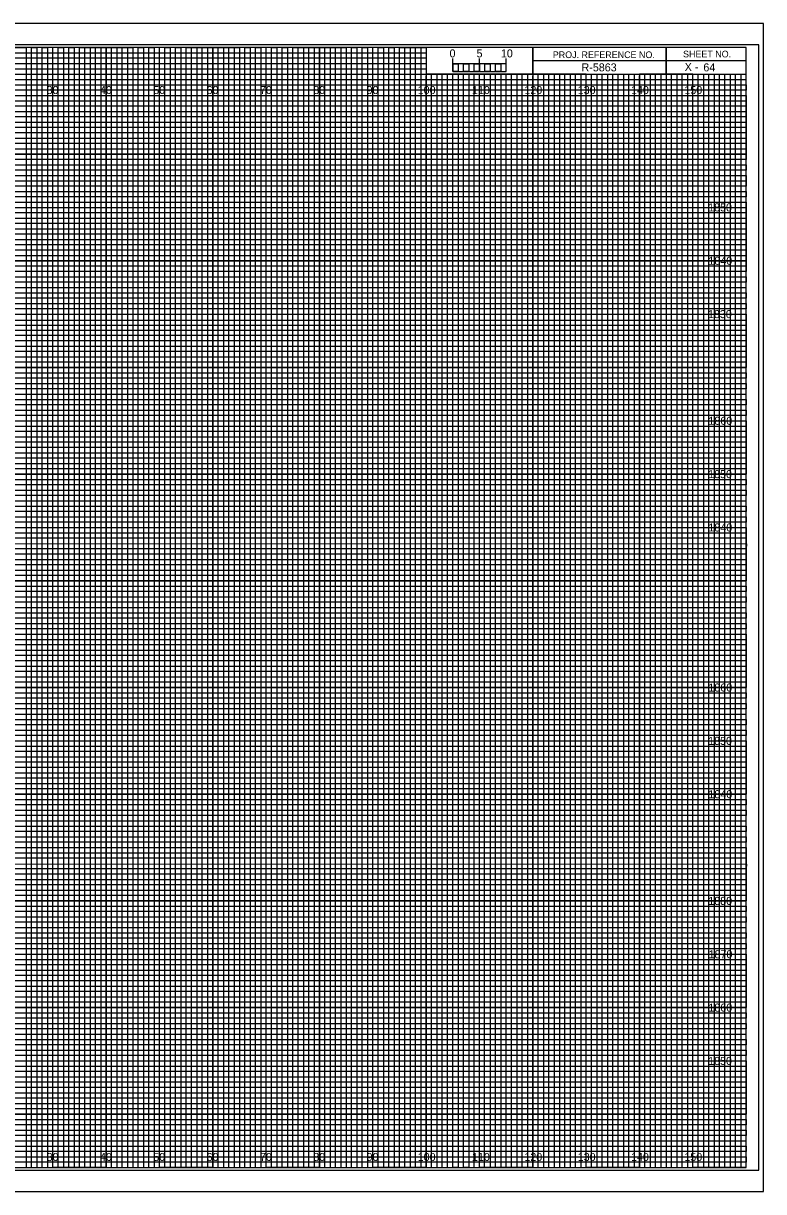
# Model space of a CAD drawing. Extents: x -13 to 323, y 656 to 874.
# Drawn here: x 184.5 to 323.3, y 655.5 to 874.5 of the extents above; entities that cross this region are included whole.
import ezdxf

# ---------------------------------------------------------------- set-up
doc = ezdxf.new("R2010")
doc.units = 0
for name, color, linetype in [('Prop XS Bar Scale Labels', 7, 'Continuous'), ('Prop XS Elevation Labels', 7, 'Continuous'), ('Prop XS Offset Labels', 7, 'Continuous'), ('Prop XS Project Number', 7, 'Continuous'), ('Prop XS Sheet Number', 7, 'Continuous'), ('Sheet Cross Section CELL', 7, 'Continuous'), ('Sheet Cross Section Grid Major CELL', 7, 'Continuous'), ('Sheet Cross Section Grid Middle CELL', 7, 'Continuous'), ('Sheet Cross Section Grid Minor 1 CELL', 7, 'Continuous'), ('Sheet Cross Section Grid Minor 2 CELL', 7, 'Continuous'), ('Sheet Cross Section Scale CELL', 7, 'Continuous'), ('Sheet Cutting Line CELL', 7, 'Continuous'), ('Sheet DOT Grid CELL', 7, 'Continuous'), ('Sheet Plot Border Inside CELL', 7, 'Continuous'), ('Sheet Plot Border Outside CELL', 7, 'Continuous')]:
    doc.layers.add(name, color=color, linetype=linetype)

msp = doc.modelspace()

# ---------------------------------------------------------------- linework, layer by layer
at = {"layer": 'Sheet Cross Section CELL'}
for p, q in [((305, 870), (305, 865)), ((305, 865), (305, 870)), ((280, 867.5), (280, 865)), ((320, 867.49), (280, 867.49)), ((280, 865), (320, 865))]:
    msp.add_line(p, q, dxfattribs=at)
for points in [[(320, 870), (0, 870), (0, 660), (320, 660)], [(280, 870), (260, 870), (260, 865.03), (280, 865.03)], [(320, 870), (280, 870), (280, 865), (320, 865)]]:
    msp.add_lwpolyline(points, close=True, dxfattribs=at)
at = {"layer": 'Sheet Cross Section Grid Major CELL'}
for p, q in [((190, 870), (180, 870)), ((190, 660), (190, 870)), ((210, 870), (200, 870)), ((200, 870), (200, 660)), ((210, 660), (210, 870)), ((230, 870), (220, 870)), ((220, 870), (220, 660)), ((230, 660), (230, 870)), ((250, 870), (240, 870)), ((240, 870), (240, 660)), ((250, 660), (250, 870)), ((260, 870), (260, 660)), ((270, 660), (270, 865)), ((290, 865), (280, 865)), ((280, 865), (280, 660)), ((290, 660), (290, 865)), ((310, 865), (300, 865)), ((300, 865), (300, 660)), ((310, 660), (310, 865)), ((200, 660), (190, 660)), ((220, 660), (210, 660)), ((240, 660), (230, 660)), ((260, 660), (250, 660)), ((280, 660), (270, 660)), ((300, 660), (290, 660)), ((320, 660), (310, 660)), ((320, 660), (320, 660))]:
    msp.add_line(p, q, dxfattribs=at)
for points in [[(0, 860), (320, 860), (320, 850), (0, 850)], [(0, 840), (320, 840), (320, 830), (0, 830)], [(0, 820), (320, 820), (320, 810), (0, 810)], [(0, 800), (320, 800), (320, 790), (0, 790)], [(0, 780), (320, 780), (320, 770), (0, 770)], [(0, 760), (320, 760), (320, 750), (0, 750)], [(0, 740), (320, 740), (320, 730), (0, 730)], [(0, 720), (320, 720), (320, 710), (0, 710)], [(0, 700), (320, 700), (320, 690), (0, 690)], [(0, 680), (320, 680), (320, 670), (0, 670)]]:
    msp.add_lwpolyline(points, dxfattribs=at)
at = {"layer": 'Sheet Cross Section Grid Middle CELL'}
for points in [[(175, 870), (185, 870), (185, 660), (195, 660), (195, 870), (205, 870), (205, 660), (215, 660), (215, 870), (225, 870), (225, 660), (235, 660), (235, 870), (245, 870), (245, 660), (255, 660), (255, 870), (259.93, 870), (260, 870), (260, 865), (264.99, 865), (264.99, 660), (275, 660), (275, 865), (285, 865), (285, 660), (295, 660), (295, 865), (305, 865), (305, 660), (315, 660), (315, 865)], [(0, 865), (275, 865)], [(0, 845), (320, 845), (320, 855), (0, 855)], [(0, 825), (320, 825), (320, 835), (0, 835)], [(0, 805), (320, 805), (320, 815), (0, 815)], [(0, 785), (320, 785), (320, 795), (0, 795)], [(0, 765), (320, 765), (320, 775), (0, 775)], [(0, 745), (320, 745), (320, 755), (0, 755)], [(0, 725), (320, 725), (320, 735), (0, 735)], [(0, 705), (320, 705), (320, 715), (0, 715)], [(0, 685), (320, 685), (320, 695), (0, 695)], [(0, 665), (320, 665), (320, 675), (0, 675)]]:
    msp.add_lwpolyline(points, dxfattribs=at)
at = {"layer": 'Sheet Cross Section Grid Minor 1 CELL'}
for p, q in [((0, 869), (260, 869)), ((260, 867.98), (0, 867.98)), ((260, 869), (260, 867.98)), ((0, 867), (260, 867)), ((260, 865.89), (0, 865.89)), ((260, 867), (260, 865.89)), ((0, 864), (320, 864))]:
    msp.add_line(p, q, dxfattribs=at)
for points in [[(0, 863), (270, 863), (320, 863), (320, 862), (0, 862)], [(0, 861), (320, 861), (320, 859), (0, 859)], [(0, 858), (320, 858), (320, 857), (0, 856.98)], [(0, 856), (320, 856), (320, 854), (0, 854)], [(0, 853), (320, 853), (320, 852), (0, 852)], [(0, 851), (320, 851), (320, 849), (0, 849)], [(0, 848), (320, 848), (320, 847), (0, 847)], [(0, 846), (320, 846), (320, 844), (0, 844)], [(0, 843), (320, 843), (320, 842), (0, 842)], [(0, 841), (320, 841), (320, 839), (0, 839)], [(0, 838), (320, 838), (320, 837), (0, 837)], [(0, 836), (320, 836), (320, 833.95), (320, 833), (320, 832), (0, 832)], [(0, 834), (320, 834), (320, 833), (0, 833)], [(0, 831), (320, 831), (320, 829), (0, 829.03)], [(0, 829.03), (320, 829), (320, 828), (0, 828)], [(0, 827), (320, 827), (320, 826), (0, 826)], [(0, 824), (320, 824), (320, 823), (0, 823)], [(0, 822), (320, 822), (320, 821), (0, 821)], [(-0.07, 818.89), (320, 818.89), (320, 817.88), (-0.07, 817.88)], [(0, 817), (320, 817), (320, 816), (0, 816)], [(0, 814), (320, 814), (320, 813), (0, 813)], [(0, 812), (320, 812), (320, 811), (0, 811)], [(0, 809), (320, 809), (320, 808), (0, 808)], [(0, 807), (320, 807), (320, 806), (0, 806)], [(0, 804), (320, 804), (320, 803), (0, 803)], [(0, 802), (320, 802), (320, 801), (0, 801)], [(0, 799), (320, 799), (319.99, 797.98), (0, 798)], [(0, 797), (320, 797), (320, 796), (0, 796)], [(0, 794), (320, 794), (320, 793), (0, 793)], [(0, 792), (320, 792), (320, 791), (0, 791)], [(0, 789), (320, 789), (320, 788), (0, 788)], [(0, 787), (320, 787), (320, 786), (0, 786)], [(0, 784), (320, 784), (320, 783), (0, 783)], [(0, 782), (320, 782), (320, 781), (0, 781)], [(0, 779), (320, 779), (320, 778), (0, 778)], [(0, 776.99), (320.07, 776.91), (320, 776), (0, 776)], [(0, 774), (320, 774), (320, 773), (0, 773)], [(0, 772), (320, 772), (320, 771), (0, 771)], [(0, 769), (320, 769), (320, 768), (0, 768)], [(0, 767), (320, 767), (320, 766), (0, 766)], [(0, 764), (320, 764), (320, 763), (0, 763)], [(0, 762), (320, 762), (320, 761), (0, 761)], [(0, 759), (320, 759), (320, 758), (0, 758)], [(0, 757), (320, 757), (320, 756), (0, 756)], [(0, 754), (320, 754), (320, 753), (0, 753)], [(0, 752), (320, 752), (320, 751), (0, 751)], [(0, 749), (320, 749), (320, 748), (0, 748)], [(0, 747), (320, 747), (320, 746), (0, 746)], [(0, 744), (320, 744), (320, 743), (0, 743)], [(0, 742), (320, 742), (320, 741), (0, 741)], [(0, 739), (320, 739), (319.99, 737.98), (0, 738)], [(0, 737), (320, 737), (320, 736), (0, 736)], [(0, 734), (320, 734), (320, 733), (0, 733)], [(0, 732), (320, 732), (320, 731), (0, 731)], [(0, 729), (320, 729), (320, 728), (0, 728)], [(0, 727), (320, 727), (320, 726), (0, 726)], [(0, 724), (320, 724), (320, 723), (0, 723)], [(0, 722), (320, 722), (320, 721), (0, 721)], [(0, 719), (320, 719), (320, 718), (0, 718)], [(0, 716.99), (320.07, 716.91), (320, 716), (0, 716)], [(0, 714), (320, 714), (320, 713), (0, 713)], [(0, 712), (320, 712), (320, 711), (0, 711)], [(0, 709), (320, 709), (320, 708), (0, 708)], [(0, 707), (320, 707), (320, 706), (0, 706)], [(0, 704), (320, 704), (320, 703), (0, 703)], [(0, 702), (320, 702), (320, 701), (0, 701)], [(0, 699), (320, 699), (320, 698), (0, 698)], [(0, 697), (320, 697), (320, 696), (0, 696)], [(0, 694), (320, 694), (320, 693), (0, 693)], [(0, 692), (320, 692), (320, 691), (0, 691)], [(0, 689), (320, 689), (320, 688), (0, 688)], [(0, 687), (320, 687), (320, 686), (0, 686)], [(0, 684), (320, 684), (320, 683), (0, 683)], [(0, 682), (320, 682), (320, 681), (0, 681)], [(0, 679), (320, 679), (320, 678), (0, 678)], [(0, 677), (320, 677), (320, 676), (0, 676)], [(0, 674), (320, 674), (320, 673), (0, 673)], [(0, 672), (320, 672), (320, 671), (0, 671)], [(0, 669), (320, 669), (320, 668), (0, 668)], [(0, 667), (320, 667), (320, 666), (0, 666)], [(0, 664), (320, 664), (320, 663), (0, 663)], [(0, 662), (320, 662), (320, 661), (0, 661)]]:
    msp.add_lwpolyline(points, dxfattribs=at)
at = {"layer": 'Sheet Cross Section Grid Minor 2 CELL'}
for p, q in [((267, 865), (266.01, 865)), ((266.01, 865), (266.01, 660)), ((267, 660), (267, 865)), ((269, 865), (268, 865)), ((268, 865), (268, 660)), ((269, 660), (269, 865)), ((266.01, 660), (265, 660)), ((268, 660), (267, 660))]:
    msp.add_line(p, q, dxfattribs=at)
for points in [[(185, 660), (186, 660), (186, 870), (187, 870), (187, 660)], [(187, 660), (188, 660), (188, 870), (189, 870), (189, 660)], [(190, 660), (191, 660), (191, 870), (192, 870), (192, 660)], [(192, 660), (193, 660), (193, 870), (194, 870), (194, 660)], [(195, 660), (196, 660), (196, 870), (197, 870), (197, 660)], [(197, 660), (198, 660), (198, 870), (199, 870), (199, 660)], [(200, 660), (201, 660), (201, 870), (202, 870), (202, 660)], [(202, 660), (203, 660), (203, 870), (204, 870), (204, 660)], [(205, 660), (206, 660), (206, 870), (207, 870), (207, 660)], [(207, 660), (208, 660), (208, 870), (209, 870), (209, 660)], [(210, 660), (211, 660), (211, 870), (212, 870), (212, 660)], [(212, 660), (213, 660), (213, 870), (214, 870), (214, 660)], [(215, 660), (216, 660), (216, 870), (217, 870), (217, 660)], [(217, 660), (218, 660), (218, 870), (219, 870), (219, 660)], [(220, 660), (221, 660), (221, 870), (222, 870), (222, 660)], [(222, 660), (223, 660), (223, 870), (224, 870), (224, 660)], [(225, 660), (226, 660), (226, 870), (227, 870), (227, 660)], [(227, 660), (228, 660), (228, 870), (229, 870), (229, 660)], [(230, 660), (231, 660), (231, 870), (232, 870), (232, 660)], [(232, 660), (233, 660), (233, 870), (234, 870), (234, 660)], [(235, 660), (236, 660), (236, 870), (237, 870), (237, 660)], [(237, 660), (238, 660), (238, 870), (239, 870), (239, 660)], [(240, 660), (241, 660), (241, 870), (242, 870), (242, 660)], [(242, 660), (243, 660), (243, 870), (244, 870), (244, 660)], [(245, 660), (246, 660), (246, 870), (247, 870), (247, 660)], [(247, 660), (248, 660), (248, 870), (249, 870), (249, 660)], [(250, 660), (251, 660), (251, 870), (252, 870), (252, 660)], [(252, 660), (253, 660), (253, 870), (254, 870), (254, 660)], [(255, 660), (256, 660), (256, 870), (257, 870), (257, 660)], [(257, 660), (258, 660), (258, 870), (259, 870), (259, 660)], [(260, 660), (261, 660), (261, 865), (262.02, 865), (262.02, 660)], [(262, 660), (263, 660), (263, 865), (263.99, 865), (263.99, 660)], [(270, 660), (270.98, 660), (270.98, 865), (272, 865), (272, 660)], [(272, 660), (273, 660), (273, 865), (274.05, 865), (274.05, 660)], [(275, 660), (276, 660), (276, 865), (277, 865), (277, 660)], [(277, 660), (278, 660), (278, 865), (279, 865), (279, 660)], [(280, 660), (281, 660), (281, 865), (282, 865), (282, 660)], [(282, 660), (283, 660), (283, 865), (284, 865), (284, 660)], [(285, 660), (286, 660), (286, 865), (287, 865), (287, 660)], [(287, 660), (288, 660), (288, 865), (289, 865), (289, 660)], [(290, 660), (291, 660), (291, 865), (292, 865), (292, 660)], [(292, 660), (293, 660), (293, 865), (294, 865), (294, 660)], [(295, 660), (296, 660), (296, 865), (297, 865), (297, 660)], [(297, 660), (298, 660), (298, 865), (299, 865), (299, 660)], [(300, 660), (301, 660), (301, 865), (302, 865), (302, 660)], [(302, 660), (303, 660), (303, 865), (304, 865), (304, 660)], [(305, 660), (306, 660), (306, 865), (307, 865), (307, 660)], [(307, 660), (308, 660), (308, 865), (309, 865), (309, 660)], [(310, 660), (311, 660), (311, 865), (312, 865), (312, 660)], [(312, 660), (313, 660), (313, 865), (314, 865), (314, 660)], [(315, 660), (316, 660), (316, 865), (317, 865), (317, 660)], [(317, 660), (318, 660), (318, 865), (319, 865), (319, 660)]]:
    msp.add_lwpolyline(points, dxfattribs=at)
at = {"layer": 'Sheet Cross Section Scale CELL'}
for p, q in [((265, 865.49), (265, 867.9)), ((265, 866.9), (265, 867.9)), ((270, 865.49), (270, 867.9)), ((275, 865.49), (275, 867.9)), ((275, 866.9), (275, 867.9))]:
    msp.add_line(p, q, dxfattribs=at)
for points in [[(275, 866.9), (265, 866.9), (265, 865.49), (275, 865.49)], [(265, 866.9), (266, 866.9), (266, 865.49), (265, 865.49)], [(267, 866.9), (268, 866.9), (268, 865.49), (267, 865.49)], [(269, 866.9), (270, 866.9), (270, 865.49), (269, 865.49)], [(271, 866.9), (272, 866.9), (272, 865.49), (271, 865.49)], [(273, 866.9), (274, 866.9), (274, 865.49), (273, 865.49)]]:
    msp.add_lwpolyline(points, close=True, dxfattribs=at)
at = {"layer": 'Sheet Cutting Line CELL'}
for p, q in [((323.3, 874.5), (-13.4, 874.5)), ((-13.4, 655.5), (323.3, 655.5))]:
    msp.add_line(p, q, dxfattribs=at)
at = {"layer": 'Sheet DOT Grid CELL'}
for p, q in [((190, 660), (190, 870)), ((200, 660), (200, 870)), ((210, 660), (210, 870)), ((220, 660), (220, 870)), ((230, 660), (230, 870)), ((240, 660), (240, 870)), ((250, 660), (250, 870)), ((260, 660), (260, 864.69)), ((270, 660), (270, 864.69)), ((280, 660), (280, 864.69)), ((290, 660), (290, 864.69)), ((300, 660), (300, 864.69)), ((310, 660), (310, 864.69)), ((0, 860), (320, 860)), ((0, 850), (320, 850)), ((0, 840), (320, 840)), ((0, 830), (320, 830)), ((0, 820), (320, 820)), ((0, 810), (320, 810)), ((0, 800), (320, 800)), ((0, 790), (320, 790)), ((0, 780), (320, 780)), ((0, 770), (320, 770)), ((0, 760), (320, 760)), ((0, 750), (320, 750)), ((0, 740), (320, 740)), ((0, 730), (320, 730)), ((0, 720), (320, 720)), ((0, 710), (320, 710)), ((0, 700), (320, 700)), ((0, 690), (320, 690)), ((0, 680), (320, 680)), ((0, 670), (320, 670))]:
    msp.add_line(p, q, dxfattribs=at)
at = {"layer": 'Sheet Plot Border Inside CELL'}
msp.add_lwpolyline([(-10.8, 659.5), (322.4, 659.5), (322.4, 870.5), (-10.8, 870.5)], close=True, dxfattribs=at)
at = {"layer": 'Sheet Plot Border Outside CELL'}
msp.add_lwpolyline([(-13.4, 655.5), (323.3, 655.5), (323.3, 874.5), (-13.4, 874.5)], close=True, dxfattribs=at)

# ---------------------------------------------------------------- texts
at = {"layer": 'Prop XS Bar Scale Labels'}
for s, p in [('5', (269.47, 868.12)), ('10', (274.04, 868.12))]:
    msp.add_text(s, height=1.5, dxfattribs=at).set_placement(p)
at = {"layer": 'Prop XS Elevation Labels'}
for s, p in [('1850', (312.9, 839.25)), ('1840', (312.95, 829.25)), ('1830', (312.86, 819.25)), ('1860', (312.95, 799.25)), ('1850', (312.9, 789.25)), ('1840', (312.95, 779.25)), ('1860', (312.95, 749.25)), ('1850', (312.9, 739.25)), ('1840', (312.95, 729.25)), ('1880', (312.92, 709.25)), ('1870', (312.98, 699.25)), ('1860', (312.95, 689.25)), ('1850', (312.9, 679.25))]:
    msp.add_text(s, height=1.5, dxfattribs=at).set_placement(p)
at = {"layer": 'Prop XS Offset Labels'}
for s, p in [('30', (188.86, 861.25)), ('40', (198.86, 861.25)), ('50', (208.86, 861.25)), ('60', (218.86, 861.25)), ('70', (228.86, 861.25)), ('80', (238.86, 861.25)), ('90', (248.86, 861.25)), ('100', (258.44, 861.25)), ('110', (268.62, 861.25)), ('120', (278.44, 861.25)), ('130', (288.44, 861.25)), ('140', (298.44, 861.25)), ('150', (308.44, 861.25)), ('30', (188.86, 661.25)), ('40', (198.86, 661.25)), ('50', (208.86, 661.25)), ('60', (218.86, 661.25)), ('70', (228.86, 661.25)), ('80', (238.86, 661.25)), ('90', (248.86, 661.25)), ('100', (258.44, 661.25)), ('110', (268.62, 661.25)), ('120', (278.44, 661.25)), ('130', (288.44, 661.25)), ('140', (298.44, 661.25)), ('150', (308.44, 661.25))]:
    msp.add_text(s, height=1.5, dxfattribs=at).set_placement(p)
at = {"layer": 'Prop XS Project Number'}
msp.add_text('R-5863', height=1.5, dxfattribs=at).set_placement((289.16, 865.5))
at = {"layer": 'Prop XS Sheet Number'}
msp.add_text('64', height=1.5, dxfattribs=at).set_placement((312, 865.5))
at = {"layer": 'Sheet Cross Section CELL'}
for s, height, p in [('PROJ. REFERENCE NO.', 1.25, (283.77, 867.99)), ('SHEET NO.', 1.25, (308.19, 868.12)), ('X -    ', 1.5, (308.5, 865.58))]:
    msp.add_text(s, height=height, dxfattribs=at).set_placement(p)
at = {"layer": 'Sheet Cross Section Scale CELL'}
msp.add_text('0', height=1.5, dxfattribs=at).set_placement((264.41, 868.12))

doc.saveas('drawing.dxf')
